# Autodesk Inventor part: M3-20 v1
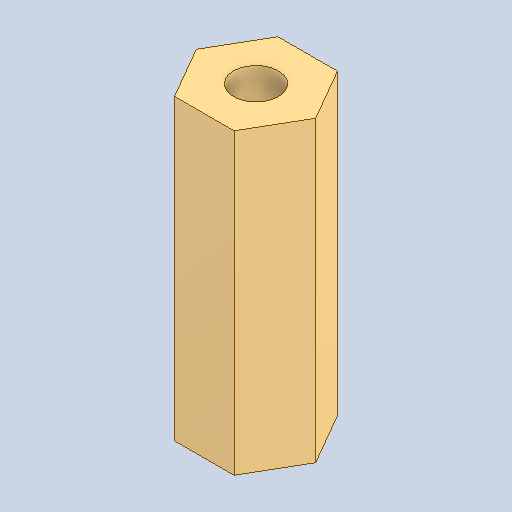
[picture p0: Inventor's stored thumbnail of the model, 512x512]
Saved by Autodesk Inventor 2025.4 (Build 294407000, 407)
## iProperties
Created: 2026-09
Part Number: M3-20 v1
Material: Generic
Document SubType Name: Modeling
Designer: AdminForWorker
Density: 1 g/cm^3
Appearance: Default
Title: M3-20 v1
Author: AdminForWorker
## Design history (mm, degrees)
feature "Body1"
body "Solid1"
